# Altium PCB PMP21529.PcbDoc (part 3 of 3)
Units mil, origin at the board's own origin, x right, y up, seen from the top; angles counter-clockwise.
Board outline 4400 x 2200 mil, 4 copper layers (Top Layer, Signal Layer 1, Signal Layer 2, Bottom Layer), stack 41.2 mil thick; 196 components, 92 nets, 502 pads, 268 vias.
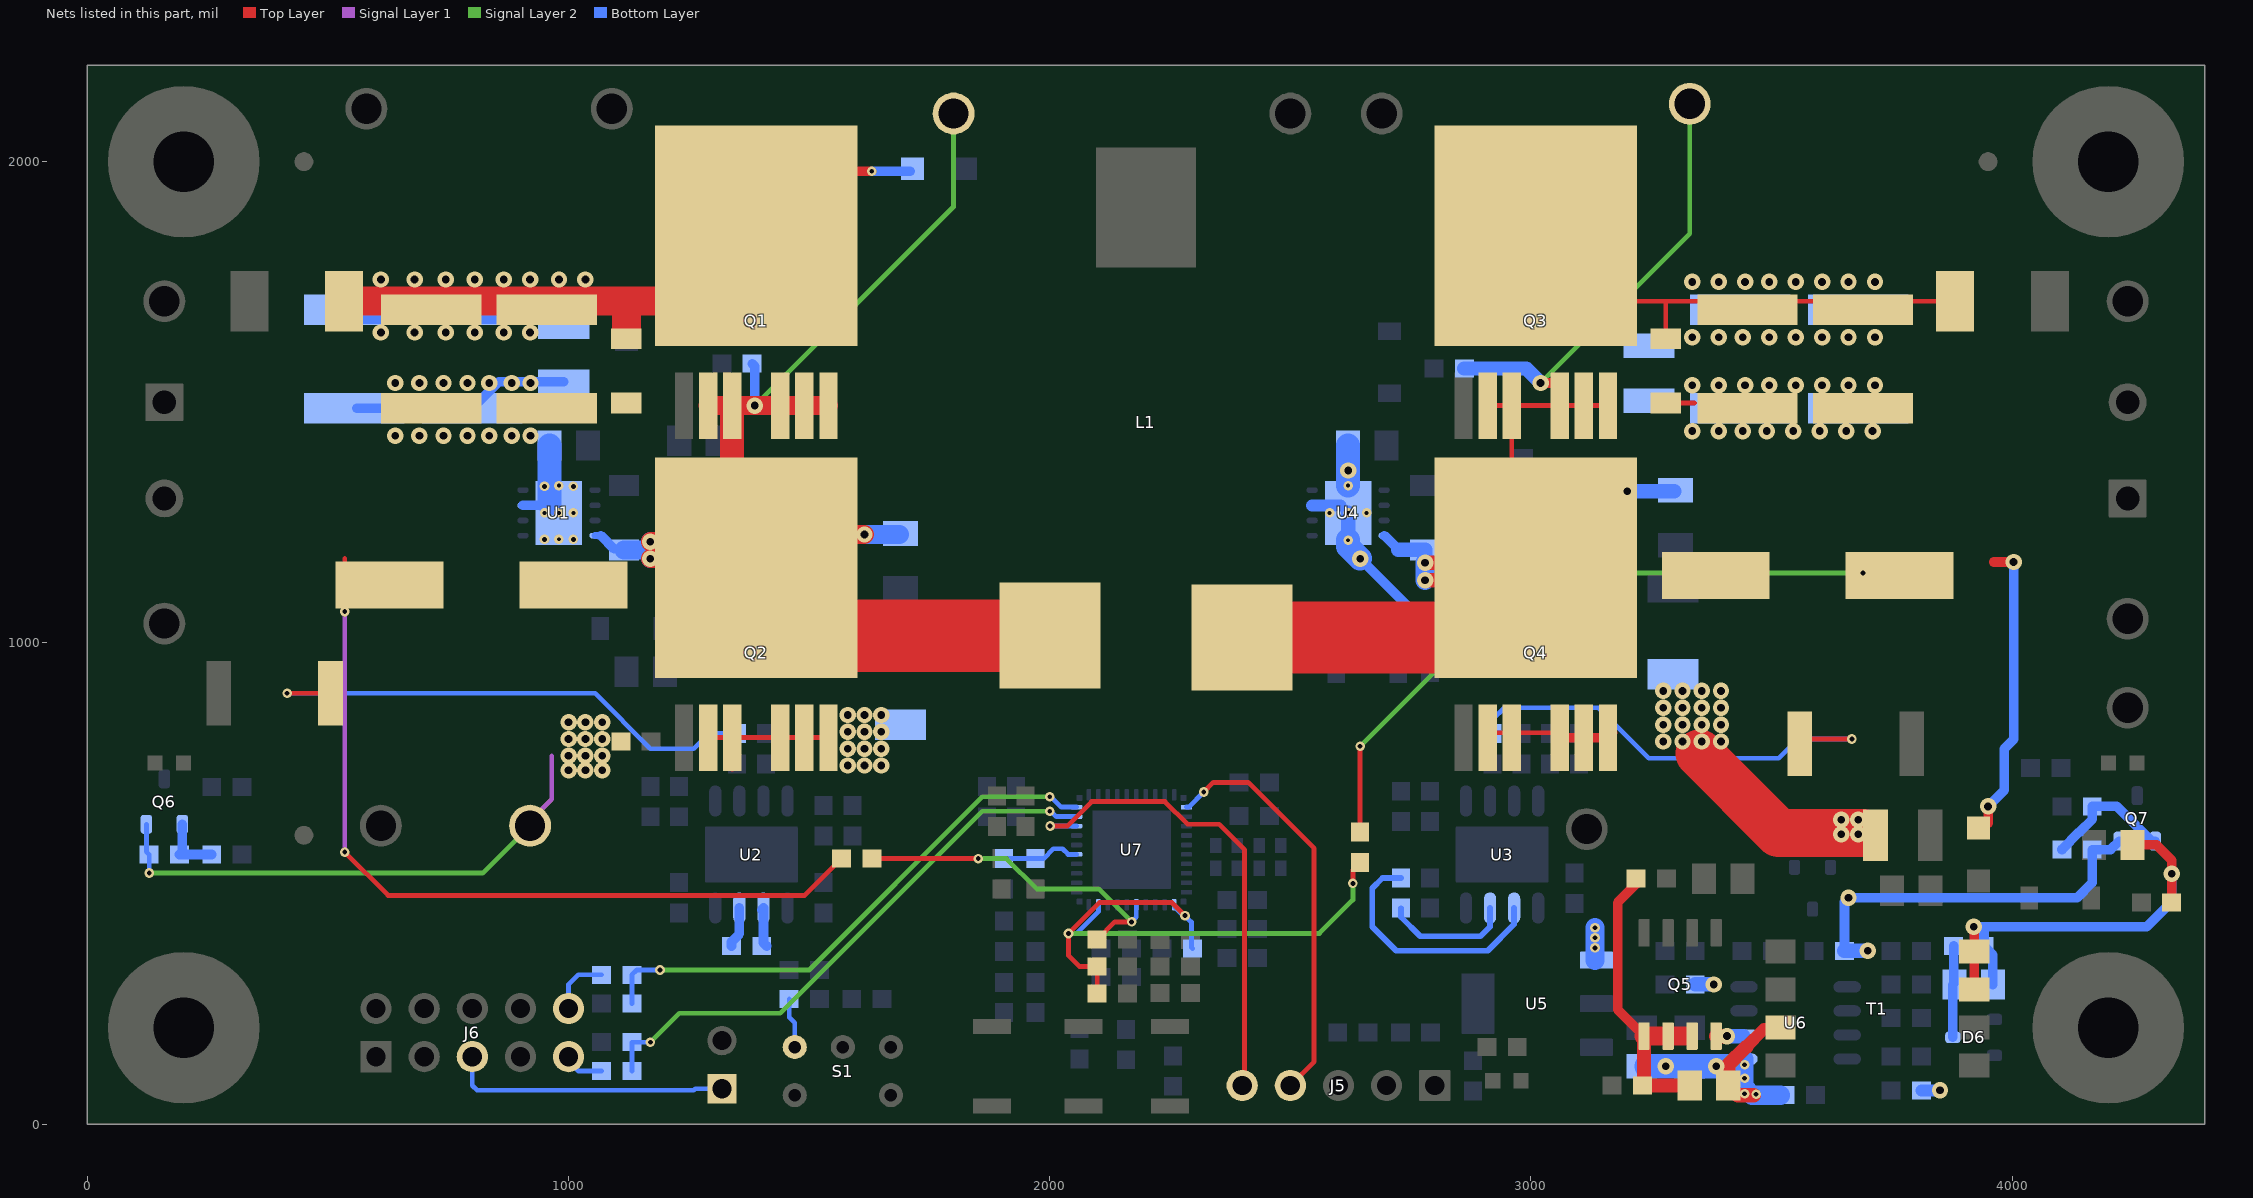
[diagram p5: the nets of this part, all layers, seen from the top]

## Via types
v1: diameter 34, hole 16, Top Layer to Bottom Layer, 162 vias
v2: diameter 20, hole 10, Top Layer to Bottom Layer, 68 vias
v3: diameter 19.68, hole 7.87, Top Layer to Bottom Layer, 30 vias
v4: diameter 19.68, hole 7.87, Top Layer to Bottom Layer, tented both sides, 8 vias

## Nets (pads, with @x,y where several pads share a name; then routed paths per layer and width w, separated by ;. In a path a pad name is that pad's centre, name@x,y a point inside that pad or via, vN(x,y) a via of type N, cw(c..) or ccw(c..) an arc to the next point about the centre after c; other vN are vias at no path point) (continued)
NetJ6_5: J6.5 J7.1 | length 584.3
  Bottom Layer w10: J6.5@800,140 800,80 810,70 1260,70 1263.39,73.39 J7.1@1318.77,73.39
NetJ6_9: J6.9 R47.1 | length 84.6
  Bottom Layer w10: J6.9@1000,140 1020,110 R47.1@1068.5,110
NetJ6_10: J6.10 R46.1 | length 126.8
  Bottom Layer w10: J6.10@1000,240 1000,290 1020,310 R46.1@1068.5,310
NetQ5_1: Q5.1 Q5.2 Q5.3 R39.2 R41.1 R44.1 | length 663.7
  Top Layer w20: R39.2@3218.5,510 3218.5,498.5 3180,460 3180,237.72 Q5.1@3235,182.72
  Top Layer w30: R41.1@3231.5,80 R44.1@3330,80 ; R41.1@3235,83.5 Q5.1@3235,182.72
  Top Layer w40: Q5.1@3235,182.72 Q5.2@3285,182.72 ; Q5.2@3275,182.72 Q5.3@3325,182.72
NetQ5_4: Q5.4 U6.6 | length 62.5
  Top Layer w20: v1(3407.28,182.72) v1@3410,180
  Top Layer w30: Q5.4@3385,182.72 v1(3407.28,182.72)
  Bottom Layer w25: U6.6@3440.43,182.72 U6.6@3442.72,185
  Bottom Layer w30: v1(3407.28,182.72) U6.6@3440.43,182.72
NetQ6_1: Q6.1 R52.2 R54.2 | length 132.2
  Bottom Layer w20: Q6.1@197.4,622.76 197.4,565.91 R54.2@191.5,560 R52.2@258.5,560
NetQ7_1: Q7.1 R53.2 R55.2 | length 277.3
  Bottom Layer w20: R55.2@4103.5,570 4103.5,570.67 4139.41,606.57 4140.08,606.57 4166.5,632.99 R53.2@4166.5,660 4217.56,660 4289.8,587.76 Q7.1@4297.4,587.76
NetR29_1: R29.1 U3.6 | length 521.2
  Bottom Layer w12: R29.1@2730,511.5 2691.5,511.5 2670,490 2670,410 2720,360 2910,360 2965,415 U3.6@2965,448.78
NetR29_2: R29.2 U3.7 | length 267.1
  Bottom Layer w12: R29.2@2730,448.5 2730,430 2770,390 2895,390 2915,410 U3.7@2915,448.78
NetR30_1: R30.1 U2.6 | length 86.4
  Bottom Layer w20: U2.6@1401.5,445.28 U2.6@1405,448.78 1405,376.5 R30.1@1411.5,370
NetR30_2: R30.2 U2.7 | length 85.6
  Bottom Layer w20: R30.2@1338.5,370 1338.5,378.5 1355,395 U2.7@1355,448.78
NetR51_1: R51.1 S1.6 | length 104.8
  Bottom Layer w10: R51.1@1458.5,260 1458.5,221.5 1470,210 S1.6@1470,160
PGND: C1.2 C2.2 C3.2 C4.2 C5.2 C6.2 C7.2 C8.2 C9.2 C10.2 C19.2 C29.2 C32.2 C35.2 C37.2 C48.2 C49.2 C50.2 C58.2 C61.2 C64.2 C65.2 NT1.1 Q2.2 Q2.3 Q2.5 Q2.6 Q2.7 Q4.2 Q4.3 Q4.5 Q4.6 Q4.7 Q6.2 Q7.2 R11.1 R12.1 R13.2 R14.1 R21.1 R22.1 R42.1 R43.2 R44.2 R54.1 R55.1 R60.1 R61.1 T1.3 TP13.1 U1.7 U1.9 U4.7 U4.9 U5.1 U6.5 | length 6832.7
  Top Layer w10: v2(415,895) R13.2@489,895 ; Q2.2@1290,803 Q2.3@1340,803 Q2.5@1440,803 Q2.6@1490,803 Q2.7@1540,803 ; Q4.2@2920,813 Q4.5@3060,813 ; C65.2@3280,1498.07 3340,1498.07 ; R14.1@3568.86,800 v2(3667,800)
  Top Layer w20: Q2.3@1340,742.28 Q2.3@1340,803 ; Q4.5@3060,803 Q4.6@3110,803 Q4.7@3160,803 Q4.7@3170,813
  Top Layer w25: 3447,160 3484,197 T1.3@3515,197
  Top Layer w30: 3447,160 3410,123 R44.2@3410,80 3430,60 v2@3463,60
  Top Layer w40: C35.2@3709.91,606 C35.2@3715.91,600
  Top Layer w100: 3350,770 3515,605 v1@3690,605
  Signal Layer 1 w10: TP13.1@920,620 920,630 965,675 965,765
  Signal Layer 2 w10: v2(128.5,521.5) 821.5,521.5 TP13.1@920,620
  Bottom Layer w10: Q6.2@122.6,622.76 122.6,565.91 R54.1@128.5,560 v2(128.5,521.5) ; v2(415,895) 1055,895 1170,780 1260,780 1291.5,811.5 R21.1@1350,811.5 ; R22.1@2920,811.5 2920,840 2945,865 3140,865 3245,760 3515,760 3555,800 v2(3667,800)
  Bottom Layer w12: U4.9@2604.25,1285.75 v3(2620,1270)
  Bottom Layer w20: C4.2@560,1487.64 C3.2@800,1487.64 855.28,1542.91 C58.2@990,1542.91 ; U1.7@905.2,1285.75 945.75,1285.75 U1.9@955,1295 ; v1(2645,1175) 2790,1030 R12.1@2790,1001.5 ; 3427.72,120 U6.5@3442.72,135 ; C48.2@3651.5,360 3651.5,461.5 v1(3660,470) 4135,470 4166.5,501.5 R55.1@4166.5,570 4204.84,570 Q7.2@4222.6,587.76
  Bottom Layer w25: U4.7@2545.2,1285.75 U4.9@2604.25,1285.75 ; R42.1@3811.5,70 v1(3850,70)
  Bottom Layer w30: v3(2620,1213.31) v3(2620,1270) ; R43.2@3341.5,290 v1(3380,290) ; C48.2@3651.5,360 v1(3700,360)
  Bottom Layer w40: v2(3133,408) v2(3133.03,386.97) v2(3133.03,365.97) U5.1@3133.03,340.55 ; U6.5@3442.72,135 3442.72,77.28 3460,60 C49.2@3518.5,60
  Bottom Layer w50: U1.9@960,1290 C19.2@960,1410 ; v3(2620,1213.31) 2620,1200 v1(2645,1175) ; v3(2620,1326.69) C29.2@2620,1410 ; C32.2@3240,120 v1(3280,120) 3427.72,120
  other v1: 3385,120 3645,602 3680,602 3645,632 3680,632 1000,735 1035,735 1070,735 1580,745 1615,745 1650,745 1000,765 1035,765 1070,765 1580,780 1615,780 1650,780 3275,795 3315,795 3355,795 3395,795 1000,800 1035,800 1070,800 1580,815 1615,815 1650,815 3275,830 3315,830 3355,830 3395,830 1000,835 1035,835 1070,835 1580,850 1615,850 1650,850 3275,865 3315,865 3355,865 3395,865 3275,900 3315,900 3355,900 3395,900 2620,1358 640,1430 690,1430 740,1430 790,1430 835,1430 882,1430 921,1430 3335,1440 3390,1440 3440,1440 3490,1440 3545,1440 3600,1440 3655,1440 3710,1440 3335,1535 3390,1535 3445,1535 3495,1535 3550,1535 3605,1535 3660,1535 3715,1535 640,1540 690,1540 740,1540 790,1540 835,1540 881.82,1540 921,1540
  other v2: 3468,62 3444,63 3444,95 3444,123 950,1215 1010,1215 950,1325 1010,1325
  other v3: 980,1215 950,1270 980,1270 1010,1270 2581.61,1270 2658.39,1270 980,1326.69
PMBUS_CLK: C59.1 R47.2 U7.9 | length 1187.8
  Signal Layer 2 w10: v2(1170,170) 1230,230 1440,230 1860,650 v2(2000,650)
  Bottom Layer w10: R47.2@1131.5,110 C59.1@1131.5,170 v2(1170,170) ; v2(2000,650) 2002.35,650 2013.45,638.9 U7.9@2055.83,638.9
PMBUS_DATA: C55.1 R46.2 U7.10 | length 1146.5
  Signal Layer 2 w10: v2(1190,320) 1500,320 1860,680 v2(2000,680)
  Bottom Layer w10: C55.1@1131.5,250 R46.2@1131.5,310 1141.5,320 v2(1190,320) ; v2(2000,680) 2002.35,680 2023.77,658.58 U7.10@2055.83,658.58
SGND: C31.2 C34.2 R58.1 R59.1 T1.7 T1.8 | length 931.7
  Top Layer w20: v1(3920,410) 3921.5,408.5 T1.8@3921.5,358.5 T1.7@3921.5,279.5 ; C34.2@4250,580 4300,580 4331.5,548.5 v1(4331.5,520) R59.1@4331.5,460
  Bottom Layer w20: v1(3920,410) 4280,410 4331.5,461.5 v1(4331.5,520) ; 3941.5,408.5 R58.1@3941.5,370 3960,351.5 C31.2@3960,290
SW1: C23.2 C62.1 L1.1 Q1.2 Q1.3 Q1.5 Q1.6 Q1.7 Q2.4 R3.2 TP2.1 U1.4 | length 2859.9
  Top Layer w20: Q2.4@1336,1210 Q2.4@1340,1206 ; Q2.4@1371,1175 Q2.4@1390,1156
  Top Layer w40: v1(1170,1175) Q2.4@1371,1175 ; v1(1170,1210) Q2.4@1336,1210 ; Q1.2@1290,1493 Q1.3@1340,1493 v1(1387,1493) Q1.5@1440,1493 Q1.6@1490,1493 Q1.7@1540,1493 ; Q2.4@1459,1225 v1(1615,1225)
  Top Layer w50: Q2.4@1340,1206 Q1.3@1340,1493 ; Q2.4@1390,1156 Q2.4@1531.16,1014.84
  Top Layer w150: Q2.4@1531.16,1014.84 L1.1@2000.2,1014.84
  Signal Layer 2 w10: v1(1387,1493) 1800,1906 TP2.1@1800,2100
  Bottom Layer w12: C23.2@1094.8,1195.2 C23.2@1112.87,1195.2
  Bottom Layer w15: U1.4@1054.8,1222.76 1067.24,1222.76
  Bottom Layer w20: 1067.24,1222.76 C23.2@1094.8,1195.2 ; R3.2@1381.5,1580 1387,1574.5 v1(1387,1493)
  Bottom Layer w25: C23.2@1112.87,1195.2 C23.2@1115,1193.07
  Bottom Layer w40: C23.2@1115,1193.07 1166,1193 ; v1(1170,1175) v1(1170,1210) ; v1(1615,1225) C62.1@1687.91,1225
SW2: C30.2 C63.1 L1.2 Q3.2 Q3.3 Q3.5 Q3.6 Q3.7 Q4.4 R4.2 TP3.1 U4.4 | length 2807.4
  Top Layer w10: Q3.2@2910,1493 Q3.3@2960,1493 ; Q4.4@2999.46,1166.54 2960,1206 Q3.3@2960,1493 ; Q3.7@3160,1493 Q3.6@3110,1493 Q3.5@3060,1493 Q3.3@2960,1493
  Top Layer w20: v1(3020,1540) 3040,1540
  Top Layer w30: v1(2780,1130) Q4.4@2984,1130 ; v1(2780,1166.54) Q4.4@2999.46,1166.54
  Top Layer w50: Q4.4@2864.91,1010.91 Q4.4@2984,1130
  Top Layer w150: L1.2@2399.8,1010.91 Q4.4@2864.91,1010.91
  Signal Layer 2 w10: v1(3020,1540) 3330,1850 TP3.1@3330,2120
  Bottom Layer w12: U4.4@2694.8,1222.76 U4.4@2695.24,1222.76
  Bottom Layer w20: U4.4@2695.24,1222.76 2724.49,1193.51
  Bottom Layer w30: 2724.49,1193.07 C30.2@2780,1193.07 v1(2780,1166.54) ; R4.2@2861.5,1570 2990,1570 v1(3020,1540) ; v1(3200,1315) C63.1@3297.91,1315
  Bottom Layer w40: v1(2780,1130) v1(2780,1166.54)
SYNC/PWM0: J5.4 U7.21 | length 856.6
  Top Layer w10: v2(2320,690) 2340,710 2412.28,710 2549.28,573 2549.28,129.28 J5.4@2500,80
  Bottom Layer w10: U7.21@2284.17,658.58 2288.58,658.58 v2(2320,690)
TCAP: J5.5 U7.8 | length 1013.8
  Top Layer w10: v2(2000.79,619.21) 2036.14,619.21 2086.93,670 2239.21,670 2286.34,622.87 2352.13,622.87 2405,570 2405,85 J5.5@2400,80
  Bottom Layer w10: v2(2000.79,619.21) U7.8@2055.83,619.21
V1+: C1.1 C2.1 C3.1 C4.1 C9.1 C58.1 C61.1 D5.2 F1.1 Q1.4 R1.2 | length 3073.3
  Top Layer w10: v2(535,565) 625,475 1490.5,475 R1.2@1567.5,552 ; v2(535,1065) 535,1175
  Top Layer w20: Q1.4@1524,1980 v2(1630,1980)
  Top Layer w60: F1.1@538.43,1710 Q1.4@1254,1710 ; C61.1@1120,1644.57 1120,1710
  Signal Layer 1 w10: v2(535,565) v2(535,1065)
  Bottom Layer w20: v2(1630,1980) D5.2@1709.88,1980
  Bottom Layer w60: C4.1@560,1692.36 C3.1@800,1692.36 954.72,1692.36
  other v1: 610,1645 680,1645 745,1645 805,1645 865,1645 920,1645 610,1755 680,1755 745,1755 805,1755 865,1755 920,1755 980,1755 1035,1755
V1_sense: C11.1 C66.1 R1.1 R9.2 U7.5 U7.35 | length 931.8
  Top Layer w10: R1.1@1637.01,551.5 v2(1851.5,551.5) ; C66.1@2098.5,383 2135.5,420 v2(2170,420)
  Signal Layer 2 w10: v2(1851.5,551.5) 1910,551.5 1972.99,488.5 2101.5,488.5 v2(2170,420)
  Bottom Layer w10: v2(1851.5,551.5) 1910,551.5 1987.15,551.5 2007.53,571.87 2026.47,571.87 2038.19,560.16 U7.5@2055.83,560.16 ; v2(2170,420) 2179.84,429.84 U7.35@2179.84,455.83
V2+: C5.1 C6.1 C7.1 C8.1 C10.1 C64.1 C65.1 D7.2 F2.2 Q3.4 R2.2 | length 3011.2
  Top Layer w10: R2.2@2645,606.5 v2(2645,785) ; Q3.4@3146,1710 3280,1710 ; C65.1@3280,1631.93 3280,1710 ; F2.2@3881.57,1710 3280,1710
  Top Layer w20: D7.2@3930,605.12 3950,625.12 v1(3950,660) ; 3962,1168 v1(4003,1168)
  Top Layer w50: Q3.4@3010,1846 Q3.4@3144.94,1980.94
  Signal Layer 2 w10: v2(2645,785) 3005,1145 v2(3690,1145)
  Bottom Layer w20: v1(3950,660) 3983.82,693.82 3983.82,780.18 4003,799.36 v1(4003,1168)
  other v1: 3335,1635 3390,1635 3440,1635 3495,1635 3550,1635 3605,1635 3660,1635 3715,1635 3335,1750 3390,1750 3445,1750 3495,1750 3550,1750 3605,1750 3660,1750 3715,1750
V2_sense: C12.1 C25.1 R2.1 R10.2 U7.31 U7.39 | length 1358.7
  Top Layer w10: R10.2@2098.5,271 C12.1@2098.5,327 2062,327 2039,350 v2(2039,396) 2103,460 2254,460 v2(2281,433) ; v2(2630,500) 2630,528.5 R2.1@2645,543.5
  Signal Layer 2 w10: v2(2039,396) 2560.28,396 2630,465.72 v2(2630,500)
  Bottom Layer w10: v2(2039,396) 2055.63,396 2101.1,441.47 U7.39@2101.1,455.83 ; U7.31@2258.7,455.71 U7.31@2258.58,455.83 2258.58,451.76 2277.34,433 v2(2281,433) 2294.5,419.5 2294.5,367 C25.1@2296.5,365
VAUXS: C31.1 D6.3 R58.2 | length 190.8
  Bottom Layer w20: D6.3@3876.69,180 3876.69,289.68 3878.5,291.5 R58.2@3878.5,370
pads on no net: D6.2 FID1.1 FID2.1 FID3.1 H1.1 H2.1 H3.1 H4.1 H5.0 H6.0 H7.0 H8.0 J6.1 J6.2 J6.3 J6.4 J6.7 J6.8 L1.3 S1.1 S1.3 S1.4 U2.9@1380,560 U3.9@2940,560 U7.16 U7.19 U7.20 U7.41@2116.06,516.06 U7.41@2116.06,570 U7.41@2116.06,623.94 U7.41@2170,516.06 U7.41@2170,570 U7.41@2170,623.94 U7.41@2223.94,516.06 U7.41@2223.94,570 U7.41@2223.94,623.94

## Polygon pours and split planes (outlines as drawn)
PGND on Signal Layer 1 "SIGNAL_LAYER_1_PGND_P054" (solid, remove dead copper, pour order 54): 3794.7,881.18 3791.18,881.18 3735,825 3651,825 3643,817 3643,782 3655,770 3720,770 3794.7,695.3 3955,535 3955,105 3890,40 3888.51,41.49 3178.51,41.49 3100,120 3100,525 3165,590 3165,647 3097,715 750,715 595,870 595,1560 630,1595 965,1595 1130,1760 3155,1760 3299.75,1615.25 3345,1570 3750,1570 3794.7,1525.3
AGND on Signal Layer 1 "SIGNAL_LAYER_1_AGND_P002" (solid, remove dead copper, pour order 2): 1115,705 3005,705 3070,640 3070,85 2995.16,10.16 1109.84,10.16 1010,110 1010,600
PGND on Top Layer "TOP_LAYER_PGND_P110" (solid, remove dead copper, pour order 110): 3245,1535 3280,1570 3750,1570 3785,1535 3785,1370 3630,1215 3575,1160 3575,555 3500,555 3350,705 3275,705 3245,735
V1+ on Top Layer "TOP_LAYER_V1+_P108" (solid, remove dead copper, pour order 108): 510,1075 450,1135 450,1850 600,2000 1195,2000 1215,1980 1215,1640 1185,1610 625,1610 580,1565 580,1355 745,1190 745,1080 740,1075
PGND on Top Layer "TOP_LAYER_PGND_P106" (solid, remove dead copper, pour order 106): 1150,843 1126,819 1126,771 1142,755 1186.8,755 1679,755 1704.5,729.5 1585,610 880,610 775,715 516,715 485,746 485,995 515,1025 750,1025 785,1060 785,1200 605,1380 605,1550 625,1570 1130,1570 1150,1550
AGND on Top Layer "TOP_LAYER_AGND_P104" (solid, remove dead copper, pour order 104): 2153,384 2153,311 2236,311 2236,319 2236,384
PGND on Top Layer "TOP_LAYER_PGND_P082" (none, remove dead copper, pour order 82): 945.8,750 1470,750 1480,740 1480,625 1465,610 1005,610 983.82,631.18
SW1 on Top Layer "TOP_LAYER_SW1_P062" (solid, remove dead copper, pour order 62): 1150,1225 1160,1235 1190,1235 1200,1225 1200,1160 1195,1155 1160,1155 1150,1165
NetD2_2 on Top Layer "TOP_LAYER_NETD2_2_P060" (solid, remove dead copper, pour order 60): 1180,880 1190,890 1220,890 1230,880 1230,815 1225,810 1190,810 1180,820
NetD1_2 on Top Layer "TOP_LAYER_NETD1_2_P056" (solid, remove dead copper, pour order 56): 1225,1535 1235,1525 1235,1470 1230,1465 1190,1465 1180,1475 1180,1525 1190,1535 1195,1535
NetD3_2 on Top Layer "TOP_LAYER_NETD3_2_P040" (solid, remove dead copper, pour order 40): 2795,840 2800,850 2805,855 2850,855 2860,845 2860,790 2855,785 2805,785 2795,795
SW2 on Top Layer "TOP_LAYER_SW2_P036" (solid, remove dead copper, pour order 36): 2772,1184 2807,1184 2807,1114 2772,1114 2760,1126 2760,1172
NetD4_2 on Top Layer "TOP_LAYER_NETD4_2_P034" (solid, remove dead copper, pour order 34): 2775,1535 2785,1545 2845,1545 2855,1535 2855,1485 2845,1475 2785,1475 2775,1485
PGND on Top Layer "TOP_LAYER_PGND_P012" (solid, remove dead copper, pour order 12): 2900,865 2900,748.5 2958.5,690 3365,690 3430,755 3430,865 3410,885 2920,885
PGND on Top Layer "TOP_LAYER_PGND_P010" (solid, remove dead copper, pour order 10): 1280,860 1280,740 1305,715 1690,715 1710,735 1710,860 1690,880 1300,880
SW1 on Top Layer "TOP_LAYER_SW1_P008" (solid, remove dead copper, pour order 8): 1280,1550 1280,1360 1550,1360 1550,1550
SW2 on Top Layer "TOP_LAYER_SW2_P006" (solid, remove dead copper, pour order 6): 2900,1550 2900,1360 3170,1360 3170,1550
PGND on Top Layer "TOP_LAYER_PGND_P074" (solid, remove dead copper, pour order 74): 945,860 970,885 1110,885 1125,870 1125,725 1115,715 959.72,715 945,729.72
PGND on Top Layer "TOP_LAYER_PGND_P094" (solid, remove dead copper, pour order 94): 3455,225 3375,145 3275,145 3260,130 3260,105 3321,44 3465,44 3470,49 3470,120 3515,165 3540,165 3550,175 3550,225
V2+ on Top Layer "TOP_LAYER_V2+_P112" (solid, remove dead copper, pour order 112): 3100,1890 3210,2000 3835,2000 3975,1860 3975,1115 3950,1090 3650,1090 3620,1120 3620,1190 3650,1220 3651.79,1218.21 3668.21,1218.21 3805,1355 3805,1590 3790,1605 3175,1605 3100,1680
NetJ3_1 on Top Layer "TOP_LAYER_NETJ3_1_P114" (solid, remove dead copper, pour order 114): 3770,950 3850,1030 3985,1030 4085,1130 4085,1265 4165,1345 4280,1345 4300,1325 4300,960 4060,720 3790,720 3770,740
NetJ1_2 on Top Layer "TOP_LAYER_NETJ1_2_P116" (solid, remove dead copper, pour order 116): 90,860 130,820 271,820 287,836 287,1258 205,1340 125,1340 90,1305
AGND on Bottom Layer "BOTTOM_LAYER_AGND_P102" (solid, remove dead copper, pour order 102): 2157,377.5 2247,377.5 2247,292.5 2157,292.5
AGND on Bottom Layer "BOTTOM_LAYER_AGND_P100" (solid, remove dead copper, pour order 100): 2290,505 2245,505 2238.9,498.9 2238.9,471.1 2245,465 2282,465 2290,473
PGND on Bottom Layer "BOTTOM_LAYER_PGND_P018" (solid, remove dead copper, pour order 18): 3415,925 3255,925 3255,775 3415,775
V1+ on Bottom Layer "BOTTOM_LAYER_V1+_P070" (solid, remove dead copper, pour order 70): 455,1768 498,1811 1024,1811 1070,1765 1070,1645 1040,1615 483,1615 455,1643
PGND on Bottom Layer "BOTTOM_LAYER_PGND_P072" (solid, remove dead copper, pour order 72): 455,1570 475,1590 1025,1590 1042,1573 1042,1477 1020,1455 998,1455 939,1396 939,1390 470,1390 455,1405
PGND on Bottom Layer "BOTTOM_LAYER_PGND_P076" (solid, remove dead copper, pour order 76): 945,840 955,850 1080,850 1090,840 1090,725 1080,715 955,715 945,725
PGND on Bottom Layer "BOTTOM_LAYER_PGND_P078" (solid, remove dead copper, pour order 78): 1560,855 1576,871 1669,871 1680,860 1680,740 1667,727 1573,727 1560,740
V2+ on Bottom Layer "BOTTOM_LAYER_V2+_P090" (solid, remove dead copper, pour order 90): 3195,1760 3230,1795 3750,1795 3785,1760 3785,1620 3755,1590 3205,1590 3195,1600
PGND on Bottom Layer "BOTTOM_LAYER_PGND_P092" (solid, remove dead copper, pour order 92): 3195,1545 3220,1570 3760,1570 3785,1545 3785,1427 3747,1389 3235,1389 3195,1429
PGND on Bottom Layer "BOTTOM_LAYER_PGND_P096" (solid, remove dead copper, pour order 96): 3584,638 3595,649 3693,649 3701,641 3701,587 3695,581 3593,581 3584,590

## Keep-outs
Keep-Out Layer:
  text ".Layer_Name" at 577,-858.49 h60

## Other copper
Top Layer:
  text ".Layer_Name" at 577,-858.49 h60
Bottom Layer:
  text ".Layer_Name" at 577,-858.49 h60

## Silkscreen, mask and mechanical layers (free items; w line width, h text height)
Top Overlay:
  region: 810,500 590,500 590,430 810,430
  text "V2+" at 4270,1780 h72.83
  text "V1+" at 10,1610 h72.83
  text "V1-" at 20,1130 h72.83
  text "V2-" at 4270,1130 h72.83
  text "'.PRJ_Number'.PCB_Rev-" at 20,440 h90
  text ".Layer_Name" at 577,-858.49 h60
Bottom Overlay:
  text ".Layer_Name" at 577,-858.49 h60
Top Paste:
  text ".Layer_Name" at 577,-858.49 h60
Bottom Paste:
  text ".Layer_Name" at 577,-858.49 h60
Top Solder:
  text ".Layer_Name" at 577,-858.49 h60
  text ".Layer_Name" at 577,-858.49 h60
Bottom Solder:
  text ".Layer_Name" at 577,-858.49 h60
Drill Guide:
  text ".Layer_Name" at 577,-858.49 h60
M1 Board Outline:
  the board outline again, w10
  text ".Layer_Name" at 577,-858.49 h60
M2 Board Dimensions:
  rectangle: 125,-400 500,-275
  rectangle: 0,-275 125,-150
  lines w7: 0,-275 1000,-275 ; 125,-400 125,-150 ; 250,-400 250,-150 ; 500,-400 500,-150 ; 750,-400 750,-150 ; 0,-400 0,-150 1000,-150 1000,-400 0,-400
  text ".Layer_Name" at 577,-858.49 h60
M3 3D STEP Top:
  text ".Layer_Name" at 577,-858.49 h60
M4 3D STEP Bottom:
  text ".Layer_Name" at 577,-858.49 h60
M5 Assembly Top:
  lines w10: -292,-930.17 6308,-930.17 ; -292,-726.83 6310,-726.83 ; -292,-523.5 -292,-1133.5 3713,-1133.5 6310,-1133.5 6310,-523.5 -291.5,-523.5 -291.5,-1133.5 1284,-1133.5 ; 2173,-1133.5 2173,-523.5 ; 3440,-726.83 3440,-523.5 ; 4280,-726.83 4280,-523.5 ; 4902,-1140 4902,-937.17
  text "COMPONENTS MARKED 'DNP' SHOULD NOT BE POPULATED." at 1153.5,-318.5 h60
  text "ASSEMBLY VARIANT:" at 1153,-434 h60
  text ".VariantName" at 2189,-434 h60
  text "PCB VIEWED FROM TOP SIDE" at -228.5,-655.67 h60
  text "BOARD #:" at 2248,-655.67 h60
  text ".PRJ_Number" at 2793.5,-655.67 h60
  text "REV:" at 3638,-655.67 h60
  text ".PCB_Rev" at 3929.5,-655.67 h60
  text "SVN REV:" at 4476,-655.67 h60
  text ".VersionControl_RevNumber" at 4982,-655.67 h60
  text "TID #:" at 2248,-859 h60
  text ".TID" at 2793.5,-859 h60
  text "PLOT NAME =" at -228.5,-1064.34 h60
  text ".plot_File_Name" at 577,-1064.34 h60
  text "GENERATED    :" at 2250,-1064.34 h60
  text ".Print_Date" at 3119.5,-1064.34 h60
  text ".Print_Time" at 3848.5,-1064.34 h60
  text "TEXAS INSTRUMENTS" at 5113,-1064.34 h60
M6 Assembly Bottom:
  lines w10: -292.5,-727.33 6309.5,-727.33 ; -290.5,-930.67 6309.5,-930.67 ; 1115.5,-1140.5 1115.5,-937.67 ; 1737.5,-727.33 1737.5,-524 ; 2577.5,-727.33 2577.5,-524 ; 3844.5,-1134 3844.5,-524 ; 4733.5,-1134 6309,-1134 6309,-524 -292.5,-524 -292.5,-1134 2304.5,-1134 6309.5,-1134 6309.5,-524
  text "COMPONENTS MARKED 'DNP' SHOULD NOT BE POPULATED." at 6102,-318 h60
  text ".VariantName" at 5058,-434 h60
  text "ASSEMBLY VARIANT:" at 6097,-434 h60
  text ".VersionControl_RevNumber" at 1035.5,-656.17 h60
  text "SVN REV:" at 1541.5,-656.17 h60
  text ".PCB_Rev" at 2088,-656.17 h60
  text "REV:" at 2379.5,-656.17 h60
  text ".PRJ_Number" at 3224,-656.17 h60
  text "BOARD #:" at 3769.5,-656.17 h60
  text "PCB VIEWED FROM BOTTOM SIDE" at 6246,-656.17 h60
  text ".TID" at 3224,-859.5 h60
  text "TID #:" at 3769.5,-859.5 h60
  text "TEXAS INSTRUMENTS" at 904.5,-1064.84 h60
  text ".Print_Time" at 2169,-1064.84 h60
  text ".Print_Date" at 2898,-1064.84 h60
  text "GENERATED    :" at 3767.5,-1064.84 h60
  text ".plot_File_Name" at 5440.5,-1064.84 h60
  text "PLOT NAME =" at 6246,-1064.84 h60
M9 Title Sheet:
  drawing of 57 lines, arcs and shapes, not listed
  text "1" at 739.84,8036.5 h70
  text "2" at 3235.5,8036.5 h70
  text "3" at 5724.84,8036.5 h70
  text "4" at 8231.51,8036.5 h70
  text "5" at 10730.5,8036.5 h70
  text "6" at 13235.5,8036.5 h70
  text "A" at -416.5,6893.5 h70
  text "A" at 14383.5,6893.5 h70
  text "B" at -416.5,4513.5 h70
  text "B" at 14383.5,4513.5 h70
  text "C" at -416.5,2138.5 h70
  text "C" at 14383.5,2138.5 h70
  text "PROJECT TITLE:" at 11343.5,277.5 h45
  text ".PRJ_Title" at 11393.5,144.17 h70
  text "DESIGNED FOR:" at 11343.5,-23.5 h45
  text ".PRJ_Customer" at 11393.5,-163.5 h70
  text "D" at -416.5,-231.5 h70
  text "D" at 14383.5,-231.5 h70
  text "FILE NAME:" at 11343.5,-323.5 h45
  text ".PCB_File_Name_No_Path" at 11393.5,-443.5 h70
  text "Texas Instruments (TI) and/or its licensors do not warrant the accuracy or completeness of this specification" at 6374,-605.34 h45
  text "ENGINEER:" at 11343.5,-613.5 h45
  text "LAYOUT BY:" at 12848.5,-613.5 h45
  text "or any information contained therein. TI and/or its licensors do not warrant that this design will meet" at 6329.01,-718 h45
  text ".PRJ_Engineer" at 11393.5,-768.49 h70
  text ".PCB_Layout" at 12899,-768.49 h70
  text "the specifications, will be suitable for your application or fit for any particular purpose, or will operate in" at 6329.01,-830.67 h45
  text ".Layer_Name" at 577,-858.49 h60
  text "ALTIUM DESIGNER VERSION:" at 12848.5,-923.5 h45
  text "an implementation. TI and/or its licensors do not warrant that the design is production worthy. You should" at 6329.01,-943.33 h45
  text "completely validate and test your design implementation to confirm the system functionality for your application." at 6374,-1056 h45
  text ".print_Scale" at 11393.5,-1056.83 h70
  text ".Application_BuildNumber" at 12899,-1056.83 h70
  text "1" at 739.84,-1263.5 h70
  text "2" at 3235.5,-1263.5 h70
  text "3" at 5724.84,-1263.5 h70
  text "4" at 8231.51,-1263.5 h70
  text "5" at 10730.5,-1263.5 h70
  text "6" at 13235.5,-1263.5 h70
M10 Fab Notes:
  drawing of 189 lines, arcs and shapes, not listed
  text "DESIGN INFORMATION" at 12382.02,6356.17 h60
  text "MIN. TRACK WIDTH:" at 11737.46,6224.05 h60
  text "8" at 12833.7,6224.05 h60
  text "MIL" at 12988.46,6224.05 h60
  text "MIN. CLEARANCE:" at 11737.46,6099.92 h60
  text "0.2" at 12773.7,6099.93 h60
  text "mm" at 12988.46,6099.92 h60
  text "MIN. VIA PAD SIZE:" at 11737.46,5975.8 h60
  text "24" at 12803.71,5975.8 h60
  text "MIL" at 12988.46,5975.8 h60
  text "0.05mm (2MIL)" at 12432.46,5845.9 h60
  text "MINIMUM ANNULAR RING" at 11408.23,5837.67 h60
  text "EXTERNAL" at 13140.46,5837.67 h60
  text "PER" at 11608.23,5727.55 h60
  text "IPC-D-275 CLASS 2 LEVEL C" at 11828.23,5727.54 h60
  text "MIL, HOLES" at 13316.46,5627.07 h60
  text "+/-" at 12924,5618.48 h60
  text "+/-" at 13778,5618.48 h60
  text "REGISTRATION TOLERANCES:" at 11408.23,5617.42 h60
  text "METAL" at 12608,5617.42 h60
  text "5" at 13184.2,5617.42 h60
  text "3" at 14017.2,5617.42 h60
  text "MIL" at 14133.46,5617.42 h60
  text "HOLE SIZE TOLERANCE (UNLESS OTHERWISE SPECIFIED):" at 11408.23,5519.1 h60
  text "+/-" at 13778,5516.23 h60
  text "3" at 14017.2,5515.17 h60
  text "MIL" at 14133.46,5515.17 h60
  text "MATERIAL:" at 11333.46,5377.52 h60
  text "FR-4 High Tg" at 12319.9,5249 h60
  text "X" at 12175.46,5241.01 h60
  text "FR-408" at 11754.46,5236.49 h60
  text "OTHER" at 13242.46,5236.49 h60
  text "62 MIL (1.6mm) +/-10%" at 12074.56,5093.46 h60
  text "X" at 11954.46,5091.01 h60
  text "THICKNESS:" at 11408.23,5085.24 h60
  text "OTHER" at 13359.46,5085.24 h60
  text "TOLERANCE:" at 11408.23,4946.92 h60
  text "X" at 12256.46,4946.92 h60
  text "ANSI IPC-6012 TYPE 3 CLASS 2" at 12434.48,4946.92 h60
  text "OTHER +/-" at 12434.46,4802.73 h60
  text "BOW & TWIST:" at 11408.23,4657.54 h60
  text "X" at 12256.46,4657.54 h60
  text "ANSI IPC-6012 TYPE 3 CLASS 2" at 12434.48,4657.54 h60
  text "OTHER +/-" at 12434.46,4510.85 h60
  text "DRILLING:" at 11333.46,4380.23 h60
  text "NC_DRILL FILES" at 13094.46,4275.04 h60
  text "REFERENCE:" at 11408.23,4271.1 h60
  text "X" at 12065.46,4271.01 h60
  text "AS SHOWN" at 12243.46,4271.1 h60
  text "X" at 12966.46,4271.1 h60
  text "OTHER" at 13392.46,4128.85 h60
  text "PTH COPPER THICKNESS:" at 11407.91,4125.32 h60
  text "X" at 12547.14,4125.32 h60
  text "20-30 um" at 12675.14,4125.32 h60
  text "BOARD FINISH:" at 11333.46,3977.73 h60
  text "SILKSCREEN:" at 11488.68,3867.6 h60
  text "X" at 12446.46,3867.6 h60
  text "TOP" at 12563.46,3867.6 h60
  text "X" at 12956.46,3867.6 h60
  text "BOTTOM" at 13074.46,3867.6 h60
  text "SILKSCREEN COLOR:" at 11488.68,3712.41 h60
  text "X" at 12445.46,3712.41 h60
  text "WHITE" at 12563.46,3712.41 h60
  text "OTHER" at 13074.46,3712.41 h60
  text "X" at 12576.46,3568.96 h60
  text "GREEN" at 12694.46,3568.96 h60
  text "OTHER" at 13312.46,3568.96 h60
  text "SOLDER RESIST COLOR:" at 11488.68,3562.1 h60
  text "X" at 12576.46,3414.71 h60
  text "MATTE" at 12694.46,3414.71 h60
  text "SEMI-GLOSS" at 13312,3414.07 h60
  text "IMMERSION GOLD (ENIG)" at 12394.46,3241.94 h60
  text "ENEPIG" at 13732,3234.72 h60
  text "SURFACE FINISH:" at 11333.46,3233.72 h60
  text "X" at 12216.46,3233.72 h60
  text "IMM. TIN/SILVER OR EQUIV" at 11663,3096.4 h60
  text "OTHER" at 13094.46,3092.47 h60
  text "ARRAY/PANEL:" at 11333.46,2937.09 h60
  text "CUT AND TRIM PER M1 BOARD OUTLINE" at 12394.46,2928.87 h60
  text "N.C. ROUTE" at 12394.46,2792.9 h60
  text "X" at 13082.46,2792.9 h60
  text "V. SCORE" at 13260.46,2792.9 h60
  text "CERTIFICATION:" at 11333.46,2663.77 h60
  text "MATERIALS AND WORKMANSHIP FOR ALL PCBS" at 12058.46,2663.77 h60
  text "TO MEET OR EXCEED THE REQUIREMENTS OF:" at 12058.46,2569.71 h60
  text "X" at 11695.97,2441.08 h60
  text "ANSI IPC-A-600F CLASS ->" at 11823.96,2441.08 h60
  text "X" at 13471.97,2441.08 h60
  text "2" at 13581.96,2441.08 h60
  text "1" at 13266.96,2439.58 h60
  text "3" at 13935.96,2439.58 h60
  text "X" at 12507.97,2293.39 h60
  text "RoHS" at 12635.96,2293.39 h60
  text "OTHER" at 13280.36,2293.39 h60
  text "PER ORDER" at 13677.42,2293.39 h60
  text "ALL BOARDS MUST MEET OR EXCEED UL94-V0 REQUIREMENTS." at 11361,2139.57 h60
  text "PCB MUST BEAR THE UL94V-0 UL REGISTERED MATERIAL ID NUMBER" at 11361,2023.5 h60
  text "ADDITIONAL REQUIREMENTS:" at 11333.46,1854.08 h60
  text "MICROSECTION:" at 11408.23,1746.95 h60
  text "YES" at 12313.96,1746.95 h60
  text "REQUIRED" at 13175.46,1602.62 h60
  text "BARE BOARD ELEC. TEST:" at 11408.23,1599.76 h60
  text "NONE" at 12713.96,1599.76 h60
  text "X" at 13057.46,1599.76 h60
  text "PER ORDER" at 13767.46,1599.76 h60
  text "XX MIL VIAS REQUIRE NON-CONDUCTIVE FILL AND PLANARIZE" at 11576.38,1394.82 h59
  text "XX MIL VIAS REQUIRE CONDUCTIVE FILL AND PLANARIZE" at 11584.38,1290.84 h60
  text "OUTER XX MIL TRACES REQUIRE 50 OHM SINGLE-ENDED IMPEDANCE" at 11583.39,1127.46 h58
  text "LAYER 2 & 3 (INNER LAYERS) XX MIL WIDE, XX MIL SPACE / TRACES REQUIRE 100 OHM DIFFERENTIAL IMPEDANCE" at 11575.39,891.74 h60
  text ".Layer_Name" at 577,-858.49 h60
M11 Gerber Information:
  lines w10: -292,-930.17 6308,-930.17 ; -292,-726.83 6310,-726.83 ; -292,-523.5 -292,-1133.5 3713,-1133.5 6310,-1133.5 6310,-523.5 -291.5,-523.5 -291.5,-1133.5 1284,-1133.5 ; 2173,-1133.5 2173,-523.5 ; 3440,-726.83 3440,-523.5 ; 4280,-726.83 4280,-523.5 ; 4902,-1140 4902,-937.17
  text "ALL ARTWORK VIEWED FROM TOP SIDE" at -228.5,-655.67 h60
  text "BOARD #:" at 2248,-655.67 h60
  text ".PRJ_Number" at 2793.5,-655.67 h60
  text "REV:" at 3638,-655.67 h60
  text ".PCB_Rev" at 3929.5,-655.67 h60
  text "SVN REV:" at 4476,-655.67 h60
  text ".VersionControl_RevNumber" at 4982,-655.67 h60
  text "LAYER NAME =" at -228.5,-858.49 h60
  text "TID #:" at 2248,-859 h60
  text ".TID" at 2793.5,-859 h60
  text "PLOT NAME =" at -228.5,-1064.34 h60
  text ".plot_File_Name" at 577,-1064.34 h60
  text "GENERATED    :" at 2250,-1064.34 h60
  text ".Print_Date" at 3119.5,-1064.34 h60
  text ".Print_Time" at 3848.5,-1064.34 h60
  text "TEXAS INSTRUMENTS" at 5113,-1064.34 h60
M12 Stackup:
  drawing of 295 lines, arcs and shapes, not listed
  text "Layer" at 9797.84,7830 h60
  text "Name" at 10207.76,7830 h60
  text "Material" at 11147.5,7830 h60
  text "Thickness" at 12007.26,7830 h60
  text "Constant" at 12657.1,7830 h60
  text "Board Layer Stack" at 13226.96,7830 h60
  text "1" at 9797.84,7710 h60
  text "Top Overlay" at 10207.76,7710 h60
  text "2" at 9797.84,7590 h60
  text "Top Solder" at 10207.76,7590 h60
  text "Solder Resist" at 11147.5,7590 h60
  text "0.40mil" at 12007.26,7590 h60
  text "3.5" at 12657.1,7590 h60
  text "3" at 9797.84,7470 h60
  text "Top Layer" at 10207.76,7470 h60
  text "Copper" at 11147.5,7470 h60
  text "2.80mil" at 12007.26,7470 h60
  text "4" at 9797.84,7350 h60
  text "Dielectric1" at 10207.76,7350 h60
  text "FR-4" at 11147.5,7350 h60
  text "10.00mil" at 12007.26,7350 h60
  text "4.8" at 12657.1,7350 h60
  text "5" at 9797.84,7230 h60
  text "Signal Layer 1" at 10207.76,7230 h60
  text "Copper" at 11147.5,7230 h60
  text "2.80mil" at 12007.26,7230 h60
  text "6" at 9797.84,7110 h60
  text "Dielectric 2" at 10207.76,7110 h60
  text "FR-4" at 11147.5,7110 h60
  text "10.00mil" at 12007.26,7110 h60
  text "4.8" at 12657.1,7110 h60
  text "7" at 9797.84,6990 h60
  text "Signal Layer 2" at 10207.76,6990 h60
  text "Copper" at 11147.5,6990 h60
  text "2.80mil" at 12007.26,6990 h60
  text "8" at 9797.84,6870 h60
  text "Dielectric 3" at 10207.76,6870 h60
  text "FR-4" at 11147.5,6870 h60
  text "10.00mil" at 12007.26,6870 h60
  text "4.8" at 12657.1,6870 h60
  text "9" at 9797.84,6750 h60
  text "Bottom Layer" at 10207.76,6750 h60
  text "Copper" at 11147.5,6750 h60
  text "2.80mil" at 12007.26,6750 h60
  text "10" at 9797.84,6630 h60
  text "Bottom Solder" at 10207.76,6630 h60
  text "Solder Resist" at 11147.5,6630 h60
  text "0.40mil" at 12007.26,6630 h60
  text "3.5" at 12657.1,6630 h60
  text "11" at 9797.84,6510 h60
  text "Bottom Overlay" at 10207.76,6510 h60
  text ".Layer_Name" at 577,-858.49 h60
M13 Component Bodies Top:
  text ".Layer_Name" at 577,-858.49 h60
M14 Component Bodies Bottom:
  text ".Layer_Name" at 577,-858.49 h60
M15 Courtyards Top:
  text ".Layer_Name" at 577,-858.49 h60
M16 Courtyards Bottom:
  text ".Layer_Name" at 577,-858.49 h60
Drill Drawing:
  circle w10: c4925.9,1414.8 r22.14
  lines w10: 4903.76,1492.29 4948.04,1492.29 4948.04,1536.56 4903.76,1536.56 4903.76,1492.29 ; 4903.76,1602.98 4914.83,1602.98 4914.83,1591.91 4936.97,1591.91 4936.97,1602.98 4948.04,1602.98 4948.04,1625.11 4936.97,1625.11 4936.97,1636.18 4914.83,1636.18 4914.83,1625.11 4903.76,1625.11 4903.76,1602.98 ; 4903.76,1713.67 4925.9,1691.53 4948.04,1713.67 4925.9,1735.81 4903.76,1713.67 ; 4903.76,1835.43 4948.04,1835.43 4925.9,1791.15 4903.76,1835.43 ; 4903.76,1890.77 4925.9,1901.84 4948.04,1890.77 4936.97,1912.91 4948.04,1935.05 4925.9,1923.98 4903.76,1935.05 4914.83,1912.91 4903.76,1890.77 ; 4903.76,2001.47 4914.83,2001.47 4925.9,1990.4 4936.97,2001.47 4948.04,2001.47 4936.97,2012.54 4948.04,2023.6 4936.97,2023.6 4925.9,2034.67 4914.83,2023.6 4903.76,2023.6 4914.83,2012.54 4903.76,2001.47 ; 4903.76,2090.02 4948.04,2090.02 4948.04,2134.3 4903.76,2134.3 4903.76,2090.02 ; 4903.76,2189.64 4903.76,2200.71 4914.83,2211.78 4903.76,2222.85 4903.76,2233.92 4914.83,2233.92 4925.9,2222.85 4936.97,2233.92 4948.04,2233.92 4948.04,2222.85 4936.97,2211.78 4948.04,2200.71 4948.04,2189.64 4936.97,2189.64 4925.9,2200.71 4914.83,2189.64 4903.76,2189.64 ; 4912.62,2098.87 4939.18,2098.87 4939.18,2125.44 4912.62,2125.44 4912.62,2098.87
  lines w12: 4863,1362.78 7975.94,1362.78 ; 4863,2259.38 7975.94,2259.38 ; 5178.63,1263.15 5178.63,2359 ; 5495.82,1263.15 5495.82,2359 ; 6117.56,1263.15 6117.56,2359 ; 6361.88,1263.15 6361.88,2359 ; 6722.22,1263.15 6722.22,2359 ; 7431.73,1263.15 7431.73,2359 ; 4863,1263.15 7975.94,1263.15 7975.94,2359 4863,2359 4863,1263.15
  text "Symbol" at 4922.77,2289.26 h72
  text "Quantity" at 5208.52,2289.26 h72
  text "Finished Hole Size" at 5525.7,2289.26 h72
  text "Plated" at 6147.45,2289.26 h72
  text "Hole Type" at 6391.77,2289.26 h72
  text "Drill Layer Pair" at 6752.11,2289.26 h72
  text "Hole Tolerance" at 7461.62,2289.26 h72
  text "38" at 5208.52,2189.64 h60
  text "7.87mil (0.200mm)" at 5525.7,2189.64 h60
  text "PTH" at 6147.45,2189.64 h60
  text "Round" at 6391.77,2189.64 h60
  text "Top Layer - Bottom Layer" at 6752.11,2189.64 h60
  text "68" at 5208.52,2090.02 h60
  text "10.00mil (0.254mm)" at 5525.7,2090.02 h60
  text "PTH" at 6147.45,2090.02 h60
  text "Round" at 6391.77,2090.02 h60
  text "Top Layer - Bottom Layer" at 6752.11,2090.02 h60
  text "162" at 5208.52,1990.4 h60
  text "16.00mil (0.406mm)" at 5525.7,1990.4 h60
  text "PTH" at 6147.45,1990.4 h60
  text "Round" at 6391.77,1990.4 h60
  text "Top Layer - Bottom Layer" at 6752.11,1990.4 h60
  text "5" at 5208.52,1890.77 h60
  text "26.00mil (0.660mm)" at 5525.7,1890.77 h60
  text "PTH" at 6147.45,1890.77 h60
  text "Round" at 6391.77,1890.77 h60
  text "Top Layer - Bottom Layer" at 6752.11,1890.77 h60
  text "15" at 5208.52,1791.15 h60
  text "40.00mil (1.016mm)" at 5525.7,1791.15 h60
  text "PTH" at 6147.45,1791.15 h60
  text "Round" at 6391.77,1791.15 h60
  text "Top Layer - Bottom Layer" at 6752.11,1791.15 h60
  text "2" at 5208.52,1691.53 h60
  text "40.16mil (1.020mm)" at 5525.7,1691.53 h60
  text "PTH" at 6147.45,1691.53 h60
  text "Round" at 6391.77,1691.53 h60
  text "Top Layer - Bottom Layer" at 6752.11,1691.53 h60
  text "4" at 5208.52,1591.91 h60
  text "49.21mil (1.250mm)" at 5525.7,1591.91 h60
  text "PTH" at 6147.45,1591.91 h60
  text "Round" at 6391.77,1591.91 h60
  text "Top Layer - Bottom Layer" at 6752.11,1591.91 h60
  text "14" at 5208.52,1492.29 h60
  text "63.00mil (1.600mm)" at 5525.7,1492.29 h60
  text "PTH" at 6147.45,1492.29 h60
  text "Round" at 6391.77,1492.29 h60
  text "Top Layer - Bottom Layer" at 6752.11,1492.29 h60
  text "4" at 5208.52,1392.66 h60
  text "125.98mil (3.200mm)" at 5525.7,1392.66 h60
  text "PTH" at 6147.45,1392.66 h60
  text "Round" at 6391.77,1392.66 h60
  text "Top Layer - Bottom Layer" at 6752.11,1392.66 h60
  text "312 Total" at 5208.52,1293.04 h60
  text ".Layer_Name" at 577,-858.49 h60
M17 Embedded Cavity:
  text ".Layer_Name" at 577,-858.49 h60
M18 Embedded Assembly:
  text ".Layer_Name" at 577,-858.49 h60
M19 Embedded Keepout:
  text ".Layer_Name" at 577,-858.49 h60

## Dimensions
0,0 to 0,2200 on M2 Board Dimensions
0,0 to 4400,0 on M2 Board Dimensions
0,-400 to 1000,-400 on M2 Board Dimensions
